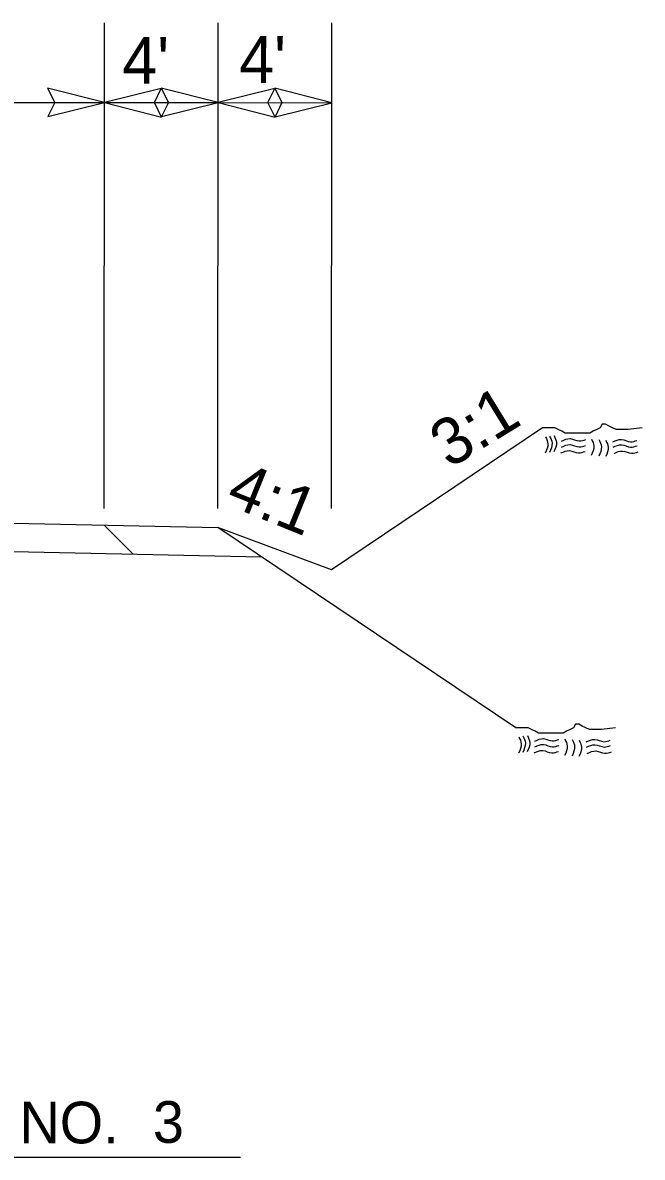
# Model space of a CAD drawing. Extents: x 2241081 to 2251104, y 658534 to 663427.
# Drawn here: x 2241909.2 to 2242018.3, y 660188.5 to 660388.4 of the extents above; entities that cross this region are included whole.
import ezdxf

# ---------------------------------------------------------------- set-up
doc = ezdxf.new("R2010")
doc.units = 0
for name, color, linetype in [('Old_Level_1', 7, 'Continuous'), ('Old_Level_2', 7, 'Continuous'), ('Prop Dimension Text', 7, 'Continuous'), ('Typical Hinge Slope Interstate CELL', 7, 'Continuous'), ('Typical Terminator CELL', 7, 'Continuous'), ('Typical Text Label CELL', 7, 'Continuous')]:
    doc.layers.add(name, color=color, linetype=linetype)

# ---------------------------------------------------------------- blocks, each defined once
blk = doc.blocks.new('TERMINATOR')
at = {"layer": 'Typical Terminator CELL'}
blk.add_lwpolyline([(-0.4687, 0.0807), (0, 0), (-0.4713, -0.0833), (-0.4114, 0)], close=True, dxfattribs=at)

msp = doc.modelspace()

# ---------------------------------------------------------------- linework, layer by layer
at = {"layer": 'Old_Level_1'}
for p, q in [((2242000.74, 660316.99), (2241963.59, 660291.99)), ((2241963.59, 660291.99), (2241943.59, 660299.45)), ((2241996.05, 660264.14), (2241943.59, 660299.45))]:
    msp.add_line(p, q, dxfattribs=at)
for points in [[(2242018.31, 660316.99), (2242015.84, 660316.69), (2242015.23, 660316.69), (2242014.3, 660316.68), (2242013.68, 660316.69), (2242013.07, 660316.99), (2242012.45, 660317.3), (2242011.84, 660317.61), (2242011.22, 660317.61), (2242010.91, 660316.99), (2242010.29, 660316.69), (2242009.68, 660316.38), (2242009.06, 660316.07), (2242008.45, 660316.07), (2242007.83, 660316.07), (2242007.21, 660316.07), (2242006.6, 660316.07), (2242005.98, 660316.07), (2242005.37, 660316.07), (2242004.75, 660316.07), (2242004.13, 660316.38), (2242003.52, 660316.69), (2242002.9, 660316.99), (2242001.98, 660316.99), (2242001.36, 660316.99), (2242000.74, 660316.99)], [(2242013.61, 660264.14), (2242011.14, 660263.84), (2242010.53, 660263.84), (2242009.6, 660263.84), (2242008.99, 660263.84), (2242008.37, 660264.14), (2242007.75, 660264.45), (2242007.14, 660264.76), (2242006.52, 660264.76), (2242006.21, 660264.14), (2242005.6, 660263.84), (2242004.98, 660263.53), (2242004.36, 660263.22), (2242003.75, 660263.22), (2242003.13, 660263.22), (2242002.52, 660263.22), (2242001.9, 660263.22), (2242001.28, 660263.22), (2242000.67, 660263.22), (2242000.05, 660263.22), (2241999.44, 660263.53), (2241998.82, 660263.84), (2241998.2, 660264.14), (2241997.28, 660264.14), (2241996.66, 660264.14), (2241996.05, 660264.14)]]:
    msp.add_lwpolyline(points, dxfattribs=at)
at = {"layer": 'Old_Level_2'}
for p, q in [((2241873.59, 660300.94), (2241943.59, 660299.45)), ((2241923.59, 660299.87), (2241928.7, 660294.76)), ((2241873.69, 660295.94), (2241951.27, 660294.28))]:
    msp.add_line(p, q, dxfattribs=at)
for points in [[(2242001.27, 660315.4), (2242001.69, 660314.16), (2242001.23, 660312.52)], [(2242001.27, 660315.4), (2242001.69, 660314.16), (2242001.23, 660312.52)], [(2242002, 660315.55), (2242002.42, 660314.3), (2242001.96, 660312.65)], [(2242002, 660315.55), (2242002.42, 660314.3), (2242001.96, 660312.65)], [(2242002.78, 660315.63), (2242003.2, 660314.38), (2242002.75, 660312.74)], [(2242002.78, 660315.63), (2242003.2, 660314.38), (2242002.75, 660312.74)], [(2242004.1, 660313.61), (2242005.6, 660314.04), (2242007.19, 660313.63), (2242008.33, 660313.89)], [(2242004.1, 660313.61), (2242005.6, 660314.04), (2242007.19, 660313.63), (2242008.33, 660313.89)], [(2242004.11, 660314.66), (2242005.6, 660315.09), (2242007.2, 660314.69), (2242008.34, 660314.94)], [(2242004.11, 660314.66), (2242005.6, 660315.09), (2242007.2, 660314.69), (2242008.34, 660314.94)], [(2242009.36, 660315.01), (2242009.78, 660313.77), (2242009.33, 660312.13)], [(2242009.36, 660315.01), (2242009.78, 660313.77), (2242009.33, 660312.13)], [(2242010.68, 660314.91), (2242011.1, 660313.67), (2242010.65, 660312.02)], [(2242010.68, 660314.91), (2242011.1, 660313.67), (2242010.65, 660312.02)], [(2242011.89, 660314.8), (2242012.31, 660313.56), (2242011.86, 660311.92)], [(2242011.89, 660314.8), (2242012.31, 660313.56), (2242011.86, 660311.92)], [(2242013.13, 660314.52), (2242014.64, 660314.95), (2242016.22, 660314.54), (2242017.37, 660314.79)], [(2242013.13, 660314.52), (2242014.64, 660314.95), (2242016.22, 660314.54), (2242017.37, 660314.79)], [(2242013.17, 660313.57), (2242014.68, 660314.01), (2242016.26, 660313.6), (2242017.41, 660313.85)], [(2242013.17, 660313.57), (2242014.68, 660314.01), (2242016.26, 660313.6), (2242017.41, 660313.85)], [(2242003.98, 660312.56), (2242005.48, 660312.98), (2242007.08, 660312.58), (2242008.23, 660312.84)], [(2242003.98, 660312.56), (2242005.48, 660312.98), (2242007.08, 660312.58), (2242008.23, 660312.84)], [(2242013.33, 660312.48), (2242014.83, 660312.91), (2242016.42, 660312.51), (2242017.57, 660312.76)], [(2241996.57, 660262.56), (2241996.99, 660261.32), (2241996.54, 660259.67)], [(2241996.57, 660262.56), (2241996.99, 660261.32), (2241996.54, 660259.67)], [(2241997.3, 660262.7), (2241997.72, 660261.45), (2241997.26, 660259.8)], [(2241997.3, 660262.7), (2241997.72, 660261.45), (2241997.26, 660259.8)], [(2241998.08, 660262.78), (2241998.51, 660261.54), (2241998.05, 660259.89)], [(2241998.08, 660262.78), (2241998.51, 660261.54), (2241998.05, 660259.89)], [(2241999.41, 660261.81), (2242000.91, 660262.24), (2242002.5, 660261.84), (2242003.64, 660262.1)], [(2241999.41, 660261.81), (2242000.91, 660262.24), (2242002.5, 660261.84), (2242003.64, 660262.1)], [(2242004.67, 660262.17), (2242005.09, 660260.93), (2242004.64, 660259.28)], [(2242004.67, 660262.17), (2242005.09, 660260.93), (2242004.64, 660259.28)], [(2242005.98, 660262.06), (2242006.4, 660260.82), (2242005.95, 660259.17)], [(2242005.98, 660262.06), (2242006.4, 660260.82), (2242005.95, 660259.17)], [(2242007.19, 660261.96), (2242007.62, 660260.71), (2242007.16, 660259.07)], [(2242007.19, 660261.96), (2242007.62, 660260.71), (2242007.16, 660259.07)], [(2242008.44, 660261.67), (2242009.94, 660262.1), (2242011.53, 660261.69), (2242012.68, 660261.95)], [(2242008.44, 660261.67), (2242009.94, 660262.1), (2242011.53, 660261.69), (2242012.68, 660261.95)], [(2241999.28, 660259.71), (2242000.79, 660260.13), (2242002.38, 660259.74), (2242003.53, 660259.99)], [(2241999.28, 660259.71), (2242000.79, 660260.13), (2242002.38, 660259.74), (2242003.53, 660259.99)], [(2241999.4, 660260.77), (2242000.91, 660261.19), (2242002.49, 660260.78), (2242003.63, 660261.04)], [(2241999.4, 660260.77), (2242000.91, 660261.19), (2242002.49, 660260.78), (2242003.63, 660261.04)], [(2242008.48, 660260.72), (2242009.98, 660261.16), (2242011.57, 660260.75), (2242012.72, 660261.01)], [(2242008.48, 660260.72), (2242009.98, 660261.16), (2242011.57, 660260.75), (2242012.72, 660261.01)], [(2242008.63, 660259.63), (2242010.13, 660260.06), (2242011.72, 660259.66), (2242012.87, 660259.92)]]:
    msp.add_spline(points, degree=3, dxfattribs=at)
at = {"layer": 'Prop Dimension Text'}
for p, q in [((2241923.59, 660302.79), (2241923.65, 660388.38)), ((2241943.59, 660302.77), (2241943.65, 660388.36)), ((2241963.59, 660302.76), (2241963.65, 660388.35)), ((2241873.64, 660374.34), (2241923.64, 660374.31)), ((2241923.64, 660374.31), (2241943.64, 660374.29)), ((2241943.64, 660374.29), (2241963.64, 660374.28))]:
    msp.add_line(p, q, dxfattribs=at)
at = {"layer": 'Typical Text Label CELL'}
msp.add_line((2241814.73, 660188.46), (2241947.59, 660188.46), dxfattribs=at)

# ---------------------------------------------------------------- block references
at = {"layer": 'Typical Terminator CELL', "xscale": 21.314641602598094, "yscale": -30.59316138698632}
for p, rotation in [((2241923.64, 660374.31), -0.03501756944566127), ((2241923.64, 660374.31), 179.96498243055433), ((2241943.64, 660374.29), -0.03501756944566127), ((2241943.64, 660374.29), 179.96498243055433), ((2241963.64, 660374.28), -0.03501756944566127)]:
    msp.add_blockref('TERMINATOR', p, dxfattribs=dict(at, rotation=rotation))

# ---------------------------------------------------------------- texts
at = {"layer": 'Prop Dimension Text'}
for p in [(2241926.77, 660377.61), (2241947.34, 660377.78)]:
    msp.add_text("4'", height=8.25, rotation=359.965, dxfattribs=at).set_placement(p)
at = {"layer": 'Typical Hinge Slope Interstate CELL'}
for s, rotation, p in [('3:1', 31.5585, (2241984.33, 660309.71)), ('4:1', 337.962, (2241944.7, 660303.6))]:
    msp.add_text(s, height=8.25, rotation=rotation, dxfattribs=at).set_placement(p)
at = {"layer": 'Typical Text Label CELL'}
for s, height, p in [('TYPICAL SECTION NO.  ', 7.3404, (2241818.67, 660190.92)), ('3 ', 7.34, (2241932.15, 660191.02))]:
    msp.add_text(s, height=height, dxfattribs=at).set_placement(p)

doc.saveas('drawing.dxf')
